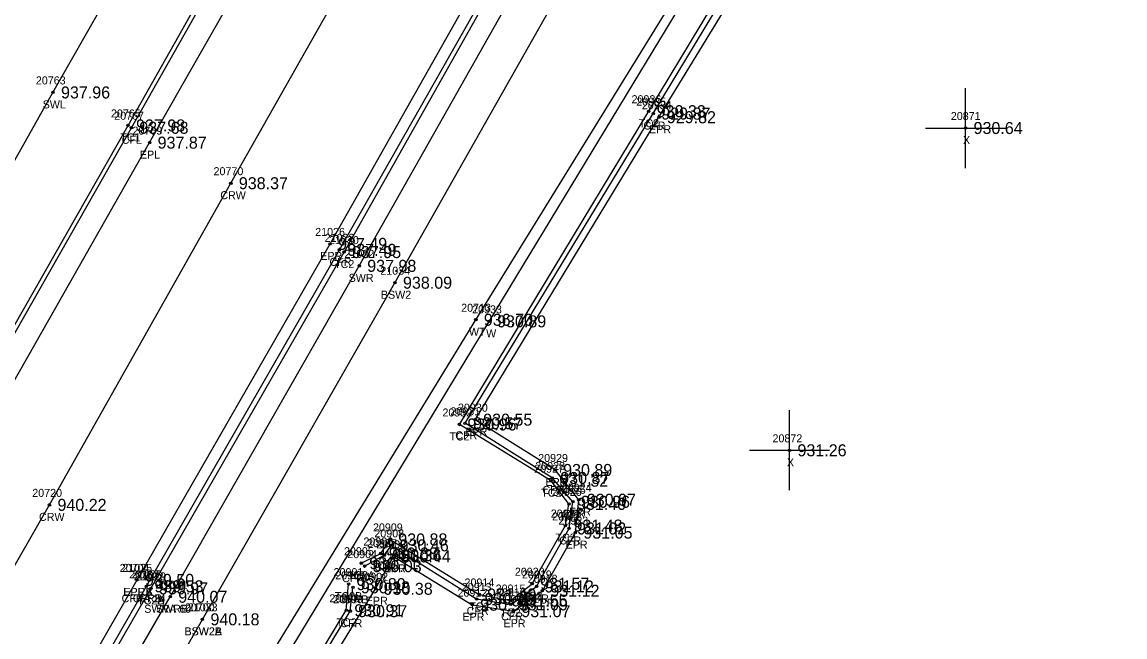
# Model space of a CAD drawing. Extents: x 1576181 to 1577685, y 1099396 to 1101490.
# Drawn here: x 1576648.9 to 1576786.7, y 1099972.4 to 1100049.3 of the extents above; entities that cross this region are included whole.
import ezdxf

# ---------------------------------------------------------------- set-up
doc = ezdxf.new("R2010")
doc.units = 0
for name, color, linetype in [('RD_DTM_BkLn1', 7, 'Continuous'), ('RD_DTM_BkLn2', 7, 'Continuous'), ('RD_EX_BldgApp', 7, 'Continuous'), ('RD_EX_Conc', 7, 'Continuous'), ('RD_EX_Conc_txCode', 7, 'Continuous'), ('RD_EX_Misc', 7, 'Continuous'), ('RD_EX_Misc_txCode', 7, 'Continuous'), ('RD_EX_Road', 7, 'Continuous'), ('RD_EX_Road_txCode', 7, 'Continuous'), ('RD_EX_TX_Conc_ELEV', 7, 'Continuous'), ('RD_EX_TX_Misc_ELEV', 7, 'Continuous'), ('RD_EX_TX_Road_ELEV', 7, 'Continuous'), ('RD_HC_Survey_ELEV', 7, 'Continuous'), ('RD_HC_Survey_txCode', 7, 'Continuous'), ('RD_SMD_Locator', 7, 'Continuous')]:
    doc.layers.add(name, color=color, linetype=linetype)

msp = doc.modelspace()

# ---------------------------------------------------------------- linework, layer by layer
at = {"layer": 'RD_DTM_BkLn1'}
msp.add_lwpolyline([(1576435.96, 1099635.47), (1576469.98, 1099685.91), (1576496.51, 1099728.46), (1576522.67, 1099770.85), (1576549.06, 1099813.4), (1576563.36, 1099837.2), (1576575.09, 1099855.95), (1576600.75, 1099898.96), (1576625.57, 1099942.14), (1576652.37, 1099988.91), (1576675.03, 1100029.12), (1576699.51, 1100072.44), (1576723.52, 1100115.7), (1576748.08, 1100158.53), (1576774.13, 1100203.85), (1576797.97, 1100246.52), (1576822.46, 1100289.82), (1576846.93, 1100333.35), (1576871.37, 1100376.46), (1576888.27, 1100406.22)], dxfattribs=at)
at = {"layer": 'RD_DTM_BkLn2'}
for points in [[(1576569.71, 1099889.13), (1576574.56, 1099891.34), (1576579.27, 1099894.47), (1576584.19, 1099899.55), (1576592.25, 1099913.59), (1576612.84, 1099949.87), (1576637.54, 1099993.05), (1576637.54, 1099993.05), (1576662.19, 1100036.34), (1576686.67, 1100079.69), (1576711.46, 1100123.12), (1576735.92, 1100166.59), (1576760.76, 1100210.19), (1576785.21, 1100253.55), (1576809.13, 1100296.43), (1576833.85, 1100340.61), (1576852.06, 1100373.52), (1576858.66, 1100385.37)], [(1576665.05, 1099978.47), (1576689.17, 1100020.51), (1576713.89, 1100064.37), (1576740.09, 1100110.61), (1576743.33, 1100115.23), (1576747.19, 1100118.34)], [(1576691.33, 1099981.62), (1576693.77, 1099982.83), (1576694.95, 1099984.59), (1576706.06, 1099977.71), (1576709.96, 1099976.95), (1576712.68, 1099979.05), (1576716.84, 1099986.32), (1576717.28, 1099989.03), (1576715.05, 1099991.93), (1576703.59, 1099998.96), (1576727.24, 1100038.12), (1576754.88, 1100083.91), (1576755.29, 1100086.86)], [(1576682.86, 1099868.56), (1576662.28, 1099880.96), (1576644.68, 1099891.53), (1576640.03, 1099896.91), (1576640.01, 1099902.65), (1576645.38, 1099914.36), (1576654.84, 1099929.02), (1576680.05, 1099970.19), (1576705.64, 1100012.05), (1576731.3, 1100053.65), (1576749.15, 1100082.97)], [(1576604.48, 1099864.36), (1576604.88, 1099870.26), (1576608.8, 1099879.99), (1576614.96, 1099891), (1576639.9, 1099934.88), (1576665.05, 1099978.47)], [(1576682.71, 1099887.7), (1576664, 1099899.28), (1576665.89, 1099902.68), (1576665.73, 1099904.83), (1576663.52, 1099907.12), (1576651.85, 1099913.48), (1576689.46, 1099975.73), (1576689.74, 1099979)]]:
    msp.add_lwpolyline(points, dxfattribs=at)
at = {"layer": 'RD_EX_BldgApp'}
msp.add_lwpolyline([(1576672.29, 1099877.61), (1576646.3, 1099893.42), (1576642.27, 1099901.79), (1576647.56, 1099912.99), (1576656.83, 1099928.62), (1576681.63, 1099969.33), (1576707.3, 1100011.85), (1576732.08, 1100052.81), (1576750.28, 1100082.51)], dxfattribs=at)
at = {"layer": 'RD_EX_Conc'}
for points in [[(1576592.25, 1099913.59), (1576580.2, 1099912.49), (1576604.17, 1099954.86), (1576628.85, 1099997.89), (1576628.85, 1099997.89), (1576652.81, 1100040.47), (1576678.28, 1100085.17), (1576702.19, 1100127.32), (1576727.43, 1100172.04), (1576752.1, 1100215.39), (1576776.49, 1100258.76), (1576788, 1100277.34), (1576801.96, 1100301.42), (1576820.18, 1100348.3), (1576829.19, 1100379.59), (1576833.87, 1100393.41), (1576838.32, 1100402.43), (1576861.82, 1100391.11)], [(1576569.87, 1099888.69), (1576574.84, 1099890.86), (1576574.84, 1099890.86), (1576579.65, 1099894.15), (1576584.72, 1099899.29), (1576592.68, 1099913.3), (1576613.45, 1099949.72), (1576638.02, 1099992.78), (1576638.02, 1099992.78), (1576662.6, 1100036.05), (1576687.14, 1100079.44), (1576711.91, 1100122.93), (1576736.42, 1100166.35), (1576761.24, 1100209.96), (1576785.67, 1100253.17), (1576809.57, 1100296.25), (1576834.31, 1100340.56), (1576852.46, 1100373.22), (1576852.46, 1100373.22), (1576859.24, 1100385.1)], [(1576664.48, 1099978.73), (1576688.59, 1100020.79), (1576713.4, 1100064.49), (1576739.81, 1100111.26), (1576742.95, 1100115.66), (1576746.94, 1100119.01)], [(1576604.88, 1099870.26), (1576606.18, 1099869.97), (1576617.18, 1099889.59), (1576642.12, 1099933.62), (1576667.46, 1099977.42), (1576667.46, 1099977.42), (1576691.07, 1100018.79), (1576716.01, 1100062.96), (1576735.12, 1100096.93), (1576741.87, 1100105.04), (1576743.62, 1100107.75)], [(1576611.55, 1099868.43), (1576613.25, 1099872.41), (1576617.21, 1099879.29), (1576621.44, 1099887.05), (1576646.34, 1099930.82), (1576671.48, 1099974.6), (1576671.48, 1099974.6), (1576695.54, 1100016.68), (1576720.22, 1100060.33), (1576739.55, 1100094.66), (1576745.88, 1100102), (1576748.75, 1100106.27)], [(1576691.74, 1099981.25), (1576694.2, 1099982.62), (1576695.12, 1099983.85), (1576705.73, 1099977.15), (1576710.01, 1099976.47), (1576713.24, 1099978.71), (1576717.29, 1099985.96), (1576717.77, 1099989.3), (1576715.19, 1099992.27), (1576704.3, 1099999.11), (1576727.81, 1100037.82), (1576755.44, 1100083.61), (1576755.82, 1100086.63)], [(1576603.88, 1099864.24), (1576604.41, 1099870.51), (1576608.23, 1099880.26), (1576614.47, 1099891.27), (1576639.43, 1099935.18), (1576664.48, 1099978.73)], [(1576682.92, 1099888.23), (1576664.94, 1099899.25), (1576666.41, 1099902.48), (1576666.21, 1099905.23), (1576663.82, 1099907.89), (1576652.51, 1099913.64), (1576689.94, 1099975.62), (1576690.28, 1099978.6)]]:
    msp.add_lwpolyline(points, dxfattribs=at)
at = {"layer": 'RD_EX_Misc'}
for p, q in [((1576766.83, 1100031.02), (1576766.83, 1100041.02)), ((1576761.83, 1100036.02), (1576771.83, 1100036.02)), ((1576744.83, 1099990.73), (1576744.83, 1100000.73)), ((1576739.83, 1099995.73), (1576749.83, 1099995.73))]:
    msp.add_line(p, q, dxfattribs=at)
at = {"layer": 'RD_EX_Road'}
for points in [[(1576574.84, 1099890.86), (1576581.17, 1099887.16), (1576595.39, 1099911.97), (1576615.87, 1099948.17), (1576640.56, 1099991.4), (1576640.56, 1099991.4), (1576664.88, 1100034.19), (1576689.84, 1100078.06), (1576714.22, 1100121.19), (1576739.08, 1100164.66), (1576764.15, 1100209.11), (1576788.31, 1100251.8), (1576812.15, 1100294.46), (1576837.06, 1100339.37), (1576855.38, 1100371.53), (1576853.98, 1100372.48), (1576862.98, 1100388.86), (1576865.16, 1100391.95), (1576873.15, 1100402.8), (1576877.45, 1100410.32)], [(1576663.31, 1099979.53), (1576687.43, 1100021.53), (1576712.03, 1100065.1), (1576738.42, 1100112.14), (1576760.61, 1100151.41), (1576785.78, 1100195.96), (1576800.59, 1100221.87), (1576817.54, 1100252.08), (1576858.25, 1100324.63), (1576880.45, 1100364.01), (1576883.5, 1100369.45), (1576896.98, 1100397.71)], [(1576683.42, 1099888.98), (1576666.06, 1099899.54), (1576667.21, 1099902.21), (1576666.94, 1099905.87), (1576664.42, 1099908.53), (1576653.81, 1099914.11), (1576693.12, 1099978.42), (1576695.37, 1099982.47), (1576705.19, 1099976.43), (1576710.33, 1099975.62), (1576713.96, 1099978.17), (1576718.08, 1099985.44), (1576718.51, 1099989.55), (1576715.55, 1099993.27), (1576705.56, 1099999.56), (1576728.51, 1100037.37), (1576758.65, 1100086.73), (1576760.7, 1100090.22), (1576769.98, 1100084.65), (1576773.31, 1100083.71), (1576776.47, 1100084.77), (1576777.62, 1100085.83)], [(1576649.23, 1099825.1), (1576640.94, 1099826.87), (1576632.86, 1099830.98), (1576616.1, 1099841.33), (1576608.21, 1099848.87), (1576606.02, 1099853.13), (1576603.89, 1099858.95), (1576602.99, 1099864.22), (1576603.41, 1099870.69), (1576607.01, 1099881.11), (1576613.26, 1099891.99), (1576638.31, 1099935.83), (1576663.31, 1099979.53)]]:
    msp.add_lwpolyline(points, dxfattribs=at)
at = {"layer": 'RD_SMD_Locator'}
for centre in [(1576652.81, 1100040.47), (1576727.24, 1100038.12), (1576727.81, 1100037.82), (1576728.51, 1100037.37), (1576662.19, 1100036.34), (1576662.6, 1100036.05), (1576766.83, 1100036.02), (1576664.88, 1100034.19), (1576675.03, 1100029.12), (1576687.43, 1100021.53), (1576688.59, 1100020.79), (1576689.17, 1100020.51), (1576691.07, 1100018.79), (1576695.54, 1100016.68), (1576705.64, 1100012.05), (1576707.3, 1100011.85), (1576703.59, 1099998.96), (1576704.3, 1099999.11), (1576705.56, 1099999.56), (1576744.83, 1099995.73), (1576715.55, 1099993.27), (1576715.05, 1099991.93), (1576715.19, 1099992.27), (1576652.37, 1099988.91), (1576717.28, 1099989.03), (1576717.77, 1099989.3), (1576718.51, 1099989.55), (1576716.84, 1099986.32), (1576717.29, 1099985.96), (1576718.08, 1099985.44), (1576694.95, 1099984.59), (1576695.12, 1099983.85), (1576693.77, 1099982.83), (1576694.2, 1099982.62), (1576695.37, 1099982.47), (1576691.33, 1099981.62), (1576691.74, 1099981.25), (1576663.31, 1099979.53), (1576663.31, 1099979.53), (1576664.48, 1099978.73), (1576664.48, 1099978.73), (1576665.05, 1099978.47), (1576665.05, 1099978.47), (1576689.74, 1099979), (1576690.28, 1099978.6), (1576693.12, 1099978.42), (1576712.68, 1099979.05), (1576713.24, 1099978.71), (1576713.96, 1099978.17), (1576667.46, 1099977.42), (1576667.46, 1099977.42), (1576705.19, 1099976.43), (1576705.73, 1099977.15), (1576706.06, 1099977.71), (1576709.96, 1099976.95), (1576710.01, 1099976.47), (1576689.46, 1099975.73), (1576689.94, 1099975.62), (1576710.33, 1099975.62), (1576671.48, 1099974.6), (1576671.48, 1099974.6)]:
    msp.add_circle(centre, 0.15, dxfattribs=at)

# ---------------------------------------------------------------- texts
at = {"layer": 'RD_EX_Conc_txCode'}
for s, p in [('20763', (1576650.67, 1100041.47)), ('20936', (1576725.1, 1100039.12)), ('SWL', (1576651.52, 1100038.47)), ('20935', (1576725.69, 1100038.82)), ('20765', (1576660.05, 1100037.34)), ('20767', (1576660.46, 1100037.05)), ('TC2', (1576726, 1100036.12)), ('CFR', (1576726.58, 1100035.82)), ('TC1', (1576661.23, 1100034.34)), ('CFL', (1576661.39, 1100034.05)), ('21028', (1576686.75, 1100021.79)), ('21030', (1576687.3, 1100021.51)), ('21032', (1576689.23, 1100019.79)), ('CFR', (1576687.36, 1100018.79)), ('TC2', (1576687.93, 1100018.51)), ('21034', (1576693.71, 1100017.68)), ('SWR', (1576689.75, 1100016.79)), ('BSW2', (1576693.78, 1100014.68)), ('20932', (1576701.47, 1099999.96)), ('20931', (1576702.46, 1100000.11)), ('TC2', (1576702.34, 1099996.96)), ('CFR', (1576703.07, 1099997.11)), ('20927', (1576712.93, 1099992.93)), ('20928', (1576713.07, 1099993.27)), ('TC2', (1576713.81, 1099989.93)), ('CFR', (1576713.96, 1099990.27)), ('20926', (1576715.14, 1099990.03)), ('20925', (1576715.65, 1099990.3)), ('20921', (1576715.01, 1099987.32)), ('20922', (1576715.17, 1099986.96)), ('TC2', (1576716.04, 1099987.03)), ('CFR', (1576716.54, 1099987.3)), ('20909', (1576692.79, 1099985.59)), ('20906', (1576691.59, 1099983.83)), ('20908', (1576692.96, 1099984.85)), ('TC2', (1576715.6, 1099984.32)), ('CFR', (1576716.06, 1099983.96)), ('20905', (1576689.17, 1099982.62)), ('20907', (1576692.05, 1099983.62)), ('TC2', (1576693.7, 1099982.59)), ('20904', (1576689.58, 1099982.25)), ('CFR', (1576693.89, 1099981.85)), ('20703', (1576662.33, 1099979.73)), ('21027', (1576662.65, 1099979.73)), ('20901', (1576687.87, 1099980)), ('TC2', (1576692.53, 1099980.83)), ('CFR', (1576692.98, 1099980.62)), ('20920', (1576710.52, 1099980.05)), ('20919', (1576711.41, 1099979.71)), ('20702', (1576662.9, 1099979.47)), ('21029', (1576663.22, 1099979.47)), ('20701', (1576665.59, 1099978.42)), ('21031', (1576665.91, 1099978.42)), ('20900', (1576688.08, 1099979.6)), ('CFRA 18', (1576688.92, 1099979.25)), ('TC2A', (1576689.6, 1099979.62)), ('20914', (1576704.23, 1099978.71)), ('TC2B', (1576688.03, 1099977)), ('20913', (1576703.89, 1099978.15)), ('20915', (1576708.12, 1099977.95)), ('20916', (1576708.16, 1099977.47)), ('TC2', (1576711.43, 1099977.05)), ('CFRA 24', (1576661.38, 1099976.73)), ('CFRB', (1576662.78, 1099976.73)), ('TC2A', (1576663.32, 1099976.47)), ('TC2B', (1576663.34, 1099976.47)), ('20700', (1576669.29, 1099975.6)), ('21033', (1576669.65, 1099975.6)), ('20898', (1576687.34, 1099976.73)), ('20899', (1576687.82, 1099976.62)), ('CFRB', (1576688.58, 1099976.6)), ('TC2', (1576704.82, 1099975.71)), ('CFR', (1576712.01, 1099976.71)), ('SWRA 60', (1576664.21, 1099975.42)), ('SWRB', (1576665.67, 1099975.42)), ('CFR', (1576704.5, 1099975.15)), ('TC2', (1576708.71, 1099974.95)), ('CFR', (1576708.79, 1099974.47)), ('TC2', (1576688.22, 1099973.73)), ('CFR', (1576688.71, 1099973.62)), ('BSW2A', (1576669.23, 1099972.6)), ('BSW2B', (1576669.25, 1099972.6))]:
    msp.add_text(s, height=1, dxfattribs=at).set_placement(p)
at = {"layer": 'RD_EX_Misc_txCode'}
for s, p in [('20871', (1576764.99, 1100037.02)), ('X', (1576766.51, 1100034.02)), ('20713', (1576703.81, 1100013.05)), ('20933', (1576705.18, 1100012.85)), ('WT', (1576704.78, 1100010.05)), ('W', (1576706.93, 1100009.85)), ('20872', (1576742.71, 1099996.73)), ('X', (1576744.51, 1099993.73))]:
    msp.add_text(s, height=1, dxfattribs=at).set_placement(p)
at = {"layer": 'RD_EX_Road_txCode'}
for s, p in [('20934', (1576726.39, 1100038.37)), ('20769', (1576662.74, 1100035.19)), ('EPR', (1576727.28, 1100035.37)), ('EPL', (1576663.67, 1100032.19)), ('21026', (1576685.57, 1100022.53)), ('EPR', (1576686.2, 1100019.53)), ('20930', (1576703.41, 1100000.56)), ('EPR', (1576704.33, 1099997.56)), ('20929', (1576713.43, 1099994.27)), ('EPR', (1576714.32, 1099991.27)), ('20924', (1576716.39, 1099990.55)), ('EPR', (1576717.28, 1099987.55)), ('20923', (1576715.96, 1099986.44)), ('20903', (1576693.21, 1099983.47)), ('EPR', (1576716.85, 1099983.44)), ('20704', (1576661.15, 1099980.53)), ('21025', (1576661.47, 1099980.53)), ('EPR', (1576694.14, 1099980.47)), ('20902', (1576690.96, 1099979.42)), ('20918', (1576712.13, 1099979.17)), ('EPRA', (1576661.59, 1099977.53)), ('EPRB', (1576661.61, 1099977.53)), ('20912', (1576703.35, 1099977.43)), ('EPR', (1576691.89, 1099976.42)), ('20917', (1576708.49, 1099976.62)), ('EPR', (1576712.73, 1099976.17)), ('EPR', (1576703.96, 1099974.43)), ('EPR', (1576709.1, 1099973.62))]:
    msp.add_text(s, height=1, dxfattribs=at).set_placement(p)
at = {"layer": 'RD_EX_TX_Conc_ELEV'}
for s, p in [('937.96', (1576653.81, 1100039.72)), ('930.33', (1576728.24, 1100037.37)), ('929.87', (1576728.81, 1100037.07)), ('937.98', (1576663.19, 1100035.59)), ('937.68', (1576663.6, 1100035.3)), ('937.49', (1576689.59, 1100020.04)), ('937.95', (1576690.17, 1100019.76)), ('937.98', (1576692.07, 1100018.04)), ('938.09', (1576696.54, 1100015.93)), ('930.96', (1576704.59, 1099998.21)), ('930.57', (1576705.3, 1099998.36)), ('931.32', (1576716.05, 1099991.18)), ('930.87', (1576716.19, 1099991.52)), ('931.40', (1576718.28, 1099988.28)), ('930.96', (1576718.77, 1099988.55)), ('931.48', (1576717.84, 1099985.57)), ('931.02', (1576718.29, 1099985.21)), ('930.88', (1576695.95, 1099983.84)), ('930.88', (1576694.77, 1099982.08)), ('930.46', (1576696.12, 1099983.1)), ('930.71', (1576692.33, 1099980.87)), ('930.36', (1576695.2, 1099981.87)), ('930.03', (1576692.74, 1099980.5)), ('939.53', (1576665.48, 1099977.98)), ('939.53', (1576665.48, 1099977.98)), ('930.80', (1576690.74, 1099978.25)), ('930.13', (1576691.28, 1099977.85)), ('931.57', (1576713.68, 1099978.3)), ('931.12', (1576714.24, 1099977.96)), ('939.97', (1576666.05, 1099977.72)), ('939.97', (1576666.05, 1099977.72)), ('940.07', (1576668.46, 1099976.67)), ('940.07', (1576668.46, 1099976.67)), ('931.49', (1576707.06, 1099976.96)), ('930.99', (1576706.73, 1099976.4)), ('931.55', (1576710.96, 1099976.2)), ('931.09', (1576711.01, 1099975.72)), ('940.18', (1576672.48, 1099973.85)), ('940.18', (1576672.48, 1099973.85)), ('930.91', (1576690.46, 1099974.98)), ('930.37', (1576690.94, 1099974.87))]:
    msp.add_text(s, height=1.5, dxfattribs=at).set_placement(p)
at = {"layer": 'RD_EX_TX_Misc_ELEV'}
for s, p in [('930.64', (1576767.83, 1100035.27)), ('936.70', (1576706.64, 1100011.3)), ('930.89', (1576708.3, 1100011.1)), ('931.26', (1576745.83, 1099994.98))]:
    msp.add_text(s, height=1.5, dxfattribs=at).set_placement(p)
at = {"layer": 'RD_EX_TX_Road_ELEV'}
for s, p in [('929.82', (1576729.51, 1100036.62)), ('937.87', (1576665.88, 1100033.44)), ('937.49', (1576688.43, 1100020.78)), ('930.55', (1576706.56, 1099998.81)), ('930.89', (1576716.55, 1099992.52)), ('930.97', (1576719.51, 1099988.8)), ('931.05', (1576719.08, 1099984.69)), ('930.44', (1576696.37, 1099981.72)), ('939.50', (1576664.31, 1099978.78)), ('939.50', (1576664.31, 1099978.78)), ('930.38', (1576694.12, 1099977.67)), ('931.12', (1576714.96, 1099977.42)), ('930.99', (1576706.19, 1099975.68)), ('931.07', (1576711.33, 1099974.87))]:
    msp.add_text(s, height=1.5, dxfattribs=at).set_placement(p)
at = {"layer": 'RD_HC_Survey_ELEV'}
for s, p in [('938.37', (1576676.03, 1100028.37)), ('940.22', (1576653.37, 1099988.16))]:
    msp.add_text(s, height=1.5, dxfattribs=at).set_placement(p)
at = {"layer": 'RD_HC_Survey_txCode'}
for s, p in [('20770', (1576672.87, 1100030.12)), ('CRW', (1576673.71, 1100027.12)), ('20720', (1576650.22, 1099989.91)), ('CRW', (1576651.06, 1099986.91))]:
    msp.add_text(s, height=1, dxfattribs=at).set_placement(p)

doc.saveas('drawing.dxf')
